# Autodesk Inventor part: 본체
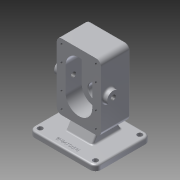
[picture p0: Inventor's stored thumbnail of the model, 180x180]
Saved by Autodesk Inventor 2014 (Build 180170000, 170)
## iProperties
Created: 2020-04
Part Number: 본체
Material: 알루미늄 6061
Document SubType Name: Modeling
Designer: kh
Density: 2.71 g/cm^3
Appearance: 알루미늄 - 평지
Mass: 1476.44 g
Surface Area: 819.925 cm^2
Volume: 544.812 cm^3
Author: kh
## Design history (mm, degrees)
sketch "스케치1"
  geometry: L1 (-60, -50)-(60, -50); L2 (60, -50)-(60, 50); L3 (60, 50)-(-60, 50); L4 (-60, 50)-(-60, -50); L5 (-60, -50)-(60, 50); L6 (60, -50)-(-60, 50); 1 further point
  constraints: 12 end point, 2 midpoint, 2 parallel, 1 horizontal, 1 perpendicular
  dimensions: "d0" = 120 distance of L1.start L1.end; "d1" = 100 distance of L1.end L2.end
extrude "돌출1" new body sketch "스케치1" distance "d2" = 10; taper "d3" = 0 deg
node "작업 평면1"
sketch "스케치2"
  geometry: L1 (120, 10)-(0, 10) reference; L2 (20, 150)-(100, 150); L3 (100, 150)-(100, 30); L4 (100, 30)-(20, 30); L5 (20, 30)-(20, 150); L6 (20, 90)-(100, 90); 2 further points
  constraints: 10 end point, 3 midpoint, 2 parallel, 1 horizontal, 1 perpendicular, 1 vertical alignment
  dimensions: "d5" = 80 distance of L2.start L2.end; "d6" = 120 distance of L2.end L3.end; "d7" = 80 distance between parallel lines of L1 L6
extrude "돌출2" join sketch "스케치2" distance "d8" = 53; taper "d9" = 0 deg
sketch "스케치3"
  geometry: L1 (120, 0)-(0, 0) reference; C1 r 19 at (60, -112); 2 further points
  constraints: 1 centre point, 1 midpoint, 1 vertical alignment
  dimensions: "d10" = 38 diameter of C1; "d11" = 112 distance from line of C1.centre L1
extrude "돌출3" join sketch "스케치3" stored distance "d12" = 53; taper "d13" = 0 deg
sketch "스케치4"
  geometry: L1 (-24, 33)-(24, 33); L2 (24, 33)-(24, -20); L3 (24, -20)-(-24, -20); L4 (-24, -20)-(-24, 33); L5 (60, 50)-(-60, 50) reference; L6 (0, 33)-(0, -20); 1 further point
  constraints: 10 end point, 2 midpoint, 2 parallel, 1 horizontal, 1 perpendicular, 1 point on line
  dimensions: "d14" = 17 distance between parallel lines of L1 L5; "d15" = 53 distance between parallel lines of L3 L1; "d16" = 48 distance between parallel lines of L4 L2
extrude "돌출4" join sketch "스케치4" stored distance "d17" = 53; taper "d18" = 0 deg
sketch "스케치5"
  geometry: L1 (-20, 0)-(-20, 53) reference; L2 (0, 0)-(-20, 0) reference; L3 (0, 53)-(0, 0) reference; L4 (0, 53)-(-20, 53) reference; L5 (0, 0)-(-20, 11.547); L6 (0, 53)-(-20, 41.453); L7 (0, 70)-(0, -30) reference; L8 (-20, 11.547)-(-20, 0); L9 (0, 0)-(-20, 0); L10 (0, 53)-(-20, 53); L11 (-20, 41.453)-(-20, 53); 1 further point
  constraints: 12 end point, 2 collinear, 2 point on line, 1 parallel, 1 perpendicular
  dimensions: "d19" = 120 deg angle of L5 L7; "d20" = 120 deg angle of L7 L6
extrude "돌출5" cut sketch "스케치5" stored distance "d21" = 53; taper "d22" = 0 deg
sketch "스케치6"
  geometry: L1 (60, 112)-(60, 68); L2 (36, 112)-(36, 68); L3 (84, 68)-(84, 112); L4 (0, 0)-(120, 0) reference; A1 r 24 centre (60, 112) between (84, 112) and (36, 112); A2 r 24 centre (60, 68) between (36, 68) and (84, 68); 3 further points
  constraints: 8 end point, 4 point on circle, 4 tangent, 2 centre point, 2 midpoint, 1 parallel, 1 vertical, 1 vertical alignment
  dimensions: "d23" = 24 radius of A1; "d24" = 44 distance of L1.end L1.start; "d25" = 90 distance from line of point (60, 90) L4
extrude "돌출6" cut sketch "스케치6" distance "d26" = 29; taper "d27" = 0 deg
sketch "스케치7"
  geometry: L1 (36, 68)-(36, 112) reference; L2 (84, 112)-(84, 68) reference; C1 r 12.5 at (60, 112); C2 r 12.5 at (60, 68); A1 r 24 centre (60, 68) between (36, 68) and (84, 68) reference; A2 r 24 centre (60, 112) between (84, 112) and (36, 112) reference; 1 further point
  constraints: 2 centre point, 2 coincident
  dimensions: "d28" = 25 diameter of C1; "d29" = 25 diameter of C2
extrude "돌출7" cut sketch "스케치7" distance "d30" = 15; taper "d31" = 0 deg
sketch "스케치8"
  geometry: C1 r 19 at (0, 0) reference; C2 r 14 at (0, 0); 1 further point
  constraints: 1 centre point, 1 coincident
  dimensions: "d32" = 28 diameter of C2
extrude "돌출8" cut sketch "스케치8" distance "d33" = 7.3; taper "d34" = 0 deg
sketch "스케치9"
  geometry: C1 r 14 at (0, 0) reference; C2 r 8.5 at (0, 0); 1 further point
  constraints: 1 centre point, 1 coincident
  dimensions: "d35" = 17 diameter of C2
extrude "돌출9" cut sketch "스케치9" stored distance "d36" = 7.3; taper "d37" = 0 deg
fillet "모깎기1" dims "d38" = 9
sketch "스케치10"
  geometry: L1 (29, 39)-(91, 39); L2 (91, 39)-(91, 141); L3 (91, 141)-(29, 141); L4 (29, 141)-(29, 39); L5 (29, 112)-(91, 112); L6 (29, 68)-(91, 68); A1 r 9 centre (29, 141) between (29, 150) and (20, 141) reference; A2 r 9 centre (91, 141) between (100, 141) and (91, 150) reference; A3 r 9 centre (29, 39) between (20, 39) and (29, 30) reference; A4 r 9 centre (91, 39) between (91, 30) and (100, 39) reference; 9 further points
  constraints: 12 end point, 9 point on line, 8 coincident, 3 perpendicular, 2 parallel, 1 horizontal
  dimensions: "d39" = 29 distance between parallel lines of L5 L3; "d40" = 44 distance between parallel lines of L6 L5
hole "구멍1" sketch "스케치10" at (29, 141), (91, 141), (91, 112), (29, 112), (29, 68), (91, 68), (91, 39), (29, 39) diameter "d41" = 4.459; stored, may be unused: countersink angle "d45" = 90 deg, drill point angle "d47" = 118 deg; dims "d42" = 10, "d43" = 4, "d44" = 2, "d46" = 12
fillet "모깎기2" dims "d48" = 10
hole "구멍2" diameter "d51" = 9; stored, may be unused: countersink angle "d55" = 90 deg, drill point angle "d57" = 118 deg; dims "d49" = 10, "d50" = 10, "d52" = 10, "d53" = 4, "d54" = 2, "d56" = 12
node "작업 평면2"
sketch "스케치11"
  geometry: L1 (141, -73)-(141, 7) reference; L2 (102, -53)-(0, -53) reference; C1 r 11 at (51, -39); 1 further point
  constraints: 1 centre point
  dimensions: "d63" = 22 diameter of C1; "d64" = 90 distance from line of C1.centre L1; "d65" = 14 distance from line of C1.centre L2
extrude "돌출10" join sketch "스케치11" stored distance "d66" = 7.3; taper "d67" = 0 deg
hole "구멍3" diameter "d70" = 8.917; stored, may be unused: countersink angle "d74" = 90 deg, drill point angle "d76" = 118 deg; dims "d68" = 10, "d69" = 10, "d71" = 10, "d72" = 4, "d73" = 2, "d75" = 12
fillet "모깎기3" dims "d77" = 3
fillet "모깎기4" dims "d78" = 3
fillet "모깎기5" dims "d79" = 3
fillet "모깎기6" dims "d80" = 3
chamfer "모따기1" distance "d81" = 1; stored, may be unused: second distance "d82" = 2, angle "d83" = 45 deg
chamfer "모따기2" distance "d84" = 0.7; stored, may be unused: second distance "d85" = 2, angle "d86" = 30 deg
fillet "모깎기7" dims "d87" = 0.5
sketch "스케치12"
  geometry: L1 (-20.739, -36.998)-(20.739, -36.998); L2 (20.739, -36.998)-(20.739, -43.002); L3 (20.739, -43.002)-(-20.739, -43.002); L4 (-20.739, -43.002)-(-20.739, -36.998); L5 (-20.739, -43.002)-(20.739, -36.998); L6 (20.739, -43.002)-(-20.739, -36.998); L7 (-50, -50)-(50, -50) reference; L8 (-60, 40)-(-60, -40) reference; 2 further points
  constraints: 4 end point, 1 midpoint, 2 other
  dimensions: "d88" = 10 distance from line of point (0, -40) L7; "d89" = 60 distance from line of point (0, -40) L8
feature "엠보싱1" sketch "스케치12" dims "d0" = 120, "d1" = 100, "d90" = 0.5, "d91" = 0
node "솔리드1"
pattern_linear "직사각형 패턴1"
mirror "대칭1"
node "투영된 루프1"
node "투영된 루프2"
other parameters: "d4" = -17, "d62" = 8
